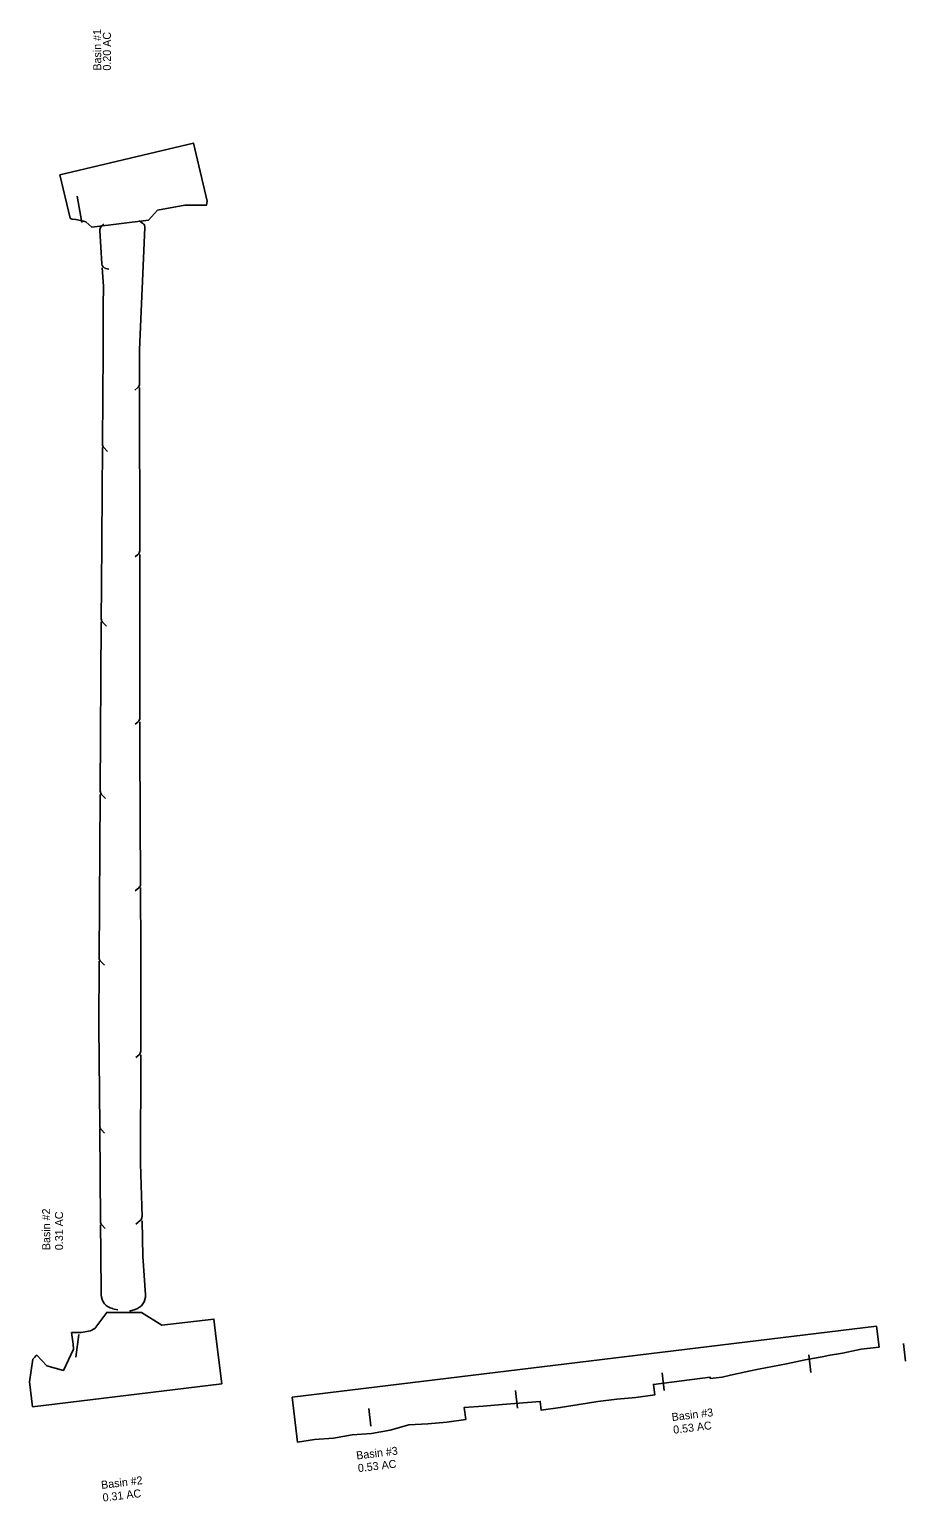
# Model space of a CAD drawing. Extents: x 18433485 to 18438479, y 7649944 to 7654998.
# Drawn here: x 18436293 to 18437212, y 7649944 to 7651489 of the extents above; entities that cross this region are included whole.
import ezdxf

# ---------------------------------------------------------------- set-up
doc = ezdxf.new("R2010")
doc.units = 0
for name, color, linetype in [('DisMisc3', 7, 'Continuous'), ('Draft_DNC', 7, 'Continuous'), ('TC_Granular', 7, 'Continuous'), ('TL_Grading', 7, 'Continuous')]:
    doc.layers.add(name, color=color, linetype=linetype)

msp = doc.modelspace()

# ---------------------------------------------------------------- linework, layer by layer
at = {"layer": 'DisMisc3'}
for p, q in [((18436342.8, 7651314.6), (18436347.8, 7651287)), ((18436370.8, 7651285.2), (18436368, 7651282.5)), ((18436411.8, 7651285.8), (18436408, 7651288.6)), ((18436408.3, 7651153.3), (18436413.9, 7651281.6)), ((18436366.4, 7651278.6), (18436368.8, 7651243.3)), ((18436369, 7651239.3), (18436370.3, 7651220.1)), ((18436372.5, 7651238.7), (18436376.1, 7651237.9)), ((18436370.3, 7651220.1), (18436370.2, 7651199.3)), ((18436370.2, 7651199.1), (18436369.9, 7651150.3)), ((18436369.9, 7651150.3), (18436369.6, 7651105.3)), ((18436408.3, 7651117.4), (18436408.3, 7651153.3)), ((18436403.4, 7651110.9), (18436406.5, 7651113.5)), ((18436408.4, 7650942.2), (18436408.3, 7651113.6)), ((18436369.6, 7651105.3), (18436369.3, 7651054.2)), ((18436369.3, 7651050.7), (18436369, 7651003.8)), ((18436370.7, 7651050.6), (18436374.7, 7651046.5)), ((18436369, 7651003.8), (18436368.6, 7650952.6)), ((18436368.6, 7650952.6), (18436368.3, 7650904.5)), ((18436403.5, 7650935.8), (18436406.6, 7650938.4)), ((18436408.5, 7650766.8), (18436408.4, 7650938.2)), ((18436368.3, 7650904.5), (18436368.1, 7650870.7)), ((18436368.1, 7650867.7), (18436367, 7650689.9)), ((18436369.5, 7650867.2), (18436373.6, 7650863.1)), ((18436403.6, 7650760.3), (18436406.7, 7650762.9)), ((18436408.5, 7650736.1), (18436408.5, 7650762.7)), ((18436409.2, 7650592.5), (18436408.5, 7650736.1)), ((18436367, 7650686.4), (18436365.9, 7650514.9)), ((18436368.4, 7650686.4), (18436372.4, 7650682.2)), ((18436403.7, 7650585.5), (18436407.4, 7650588.6)), ((18436409.5, 7650521.8), (18436409.2, 7650588.8)), ((18436365.9, 7650511.6), (18436365.5, 7650443.8)), ((18436367.3, 7650511.4), (18436371.3, 7650507.2)), ((18436409.5, 7650417), (18436409.5, 7650521.8)), ((18436365.5, 7650443.8), (18436366.4, 7650338.2)), ((18436404.5, 7650410.5), (18436407.7, 7650413.1)), ((18436409.4, 7650299), (18436409.5, 7650413.3)), ((18436366.4, 7650335.4), (18436367.2, 7650238.1)), ((18436367.8, 7650334.8), (18436371.3, 7650331.1)), ((18436410.8, 7650243.1), (18436409.4, 7650299)), ((18436367.2, 7650234.9), (18436367.5, 7650206.3)), ((18436368.6, 7650234.7), (18436372.2, 7650231)), ((18436404.4, 7650235.4), (18436409, 7650239.2)), ((18436411.8, 7650201.7), (18436410.9, 7650239.1)), ((18436367.5, 7650206.3), (18436367.9, 7650161.4)), ((18436414.5, 7650161.4), (18436411.8, 7650201.7)), ((18436380, 7650146.7), (18436385.5, 7650145.7)), ((18436397.6, 7650144.3), (18436403.5, 7650145.9)), ((18436344.5, 7650119.6), (18436341.5, 7650095.7)), ((18437211.8, 7650091.8), (18437209.6, 7650110.3)), ((18437112.6, 7650079.7), (18437110.3, 7650098.2)), ((18436958.7, 7650060.9), (18436956.5, 7650079.4)), ((18436804.9, 7650042.2), (18436802.6, 7650060.7)), ((18436651, 7650023.4), (18436648.7, 7650041.9))]:
    msp.add_line(p, q, dxfattribs=at)
for centre, radius, start, end in [((18436371.4, 7651278.9), 5, 133.3931, 183.8159), ((18436408.9, 7651281.8), 5, 357.4982, 53.4612), ((18436373.8, 7651243.6), 5, 183.8159, 255.9164), ((18436403.3, 7651117.4), 5, 309.9864, 0.0366), ((18436374.3, 7651054.1), 5, 179.6411, 224.0367), ((18436403.4, 7650942.2), 5, 309.9864, 0.0366), ((18436373.1, 7650870.7), 5, 179.6411, 224.0367), ((18436403.5, 7650766.8), 5, 309.9864, 0.0366), ((18436372, 7650689.9), 5, 179.6411, 224.0367), ((18436404.2, 7650592.4), 5, 309.9864, 0.2731), ((18436370.9, 7650514.8), 5, 179.6411, 224.0367), ((18436404.5, 7650417), 5, 309.9864, 359.9618), ((18436371.4, 7650338.3), 5, 180.4889, 224.0367), ((18436372.2, 7650238.2), 5, 180.4889, 224.0367), ((18436405.8, 7650243), 5, 309.9864, 1.3943), ((18436382.9, 7650161.5), 15, 180.4889, 259.1138), ((18436399.5, 7650160.4), 15, 285.4702, 3.8926)]:
    msp.add_arc(centre, radius, start, end, dxfattribs=at)
at = {"layer": 'Draft_DNC'}
msp.add_lwpolyline([(18436358.2, 7651281.8), (18436417.7, 7651289.3), (18436426.9, 7651299.7), (18436455.9, 7651305.1), (18436478.4, 7651304.9), (18436479.3, 7651309.4), (18436464.8, 7651370.2), (18436324.6, 7651336.8), (18436335.5, 7651291.3), (18436336.6, 7651290.8), (18436337.7, 7651290.3), (18436341.4, 7651290), (18436349.3, 7651288.3), (18436351.8, 7651287.4)], close=True, dxfattribs=at)
at = {"layer": 'TC_Granular'}
msp.add_lwpolyline([(18436488.7, 7650115), (18436494.4, 7650068), (18436296, 7650043.8), (18436292.7, 7650069.9), (18436296.3, 7650093.8), (18436298.3, 7650095.9), (18436299.5, 7650097.1), (18436300.3, 7650097.9), (18436310.8, 7650086.9), (18436328.3, 7650082), (18436339.1, 7650104.4), (18436338.5, 7650109.4), (18436337, 7650121.6), (18436346.9, 7650121.7), (18436356.7, 7650123.6), (18436361.4, 7650126.1), (18436373.9, 7650142.8), (18436410.3, 7650142.9), (18436431.6, 7650129.4), (18436486.3, 7650135.8)], close=True, dxfattribs=at)
at = {"layer": 'TL_Grading'}
msp.add_lwpolyline([(18436568.3, 7650053.9), (18437181.3, 7650128.5), (18437184, 7650106.5), (18437165.4, 7650104.2), (18437145.8, 7650100.2), (18437130.5, 7650097.5), (18437126.1, 7650096.6), (18437120.4, 7650095.6), (18437116.3, 7650094.8), (18437106.5, 7650093), (18437086.9, 7650089), (18437057.5, 7650083.1), (18437047.6, 7650081.2), (18437028.1, 7650077), (18437019.6, 7650075), (18437007, 7650073.3), (18437006.9, 7650074.7), (18436947.3, 7650067.3), (18436948.7, 7650056.3), (18436928.9, 7650053.5), (18436908.9, 7650051.6), (18436889.1, 7650049.4), (18436869.3, 7650046.2), (18436849.6, 7650042.9), (18436829.7, 7650040.2), (18436828.6, 7650049.4), (18436788.7, 7650046), (18436768.8, 7650044.3), (18436748.8, 7650043.1), (18436750.4, 7650030.3), (18436730.5, 7650027.8), (18436710.6, 7650025.9), (18436690.6, 7650024.9), (18436671.1, 7650019.1), (18436651.4, 7650015.9), (18436631.4, 7650014.3), (18436611.7, 7650011), (18436591.7, 7650009.3), (18436574.1, 7650006.6)], close=True, dxfattribs=at)

# ---------------------------------------------------------------- texts
at = {"layer": 'Draft_DNC'}
for s, p in [('Basin #1', (18436368, 7651446.3)), ('0.20 AC', (18436378.2, 7651446.3))]:
    msp.add_text(s, height=8.4, rotation=90.096, dxfattribs=at).set_placement(p)
at = {"layer": 'TC_Granular'}
for s, rotation, p in [('Basin #2', 90.096, (18436314.5, 7650208.2)), ('0.31 AC', 90.096, (18436328, 7650208.2)), ('Basin #2', 6.8081, (18436368.4, 7649957.5)), ('0.31 AC', 6.8081, (18436370, 7649944.2))]:
    msp.add_text(s, height=8.4, rotation=rotation, dxfattribs=at).set_placement(p)
at = {"layer": 'TL_Grading'}
for s, p in [('Basin #3', (18436967, 7650028.7)), ('0.53 AC', (18436968.6, 7650015.4)), ('Basin #3', (18436636.1, 7649988.4)), ('0.53 AC', (18436637.8, 7649975.1))]:
    msp.add_text(s, height=8.4, rotation=6.947, dxfattribs=at).set_placement(p)

doc.saveas('drawing.dxf')
